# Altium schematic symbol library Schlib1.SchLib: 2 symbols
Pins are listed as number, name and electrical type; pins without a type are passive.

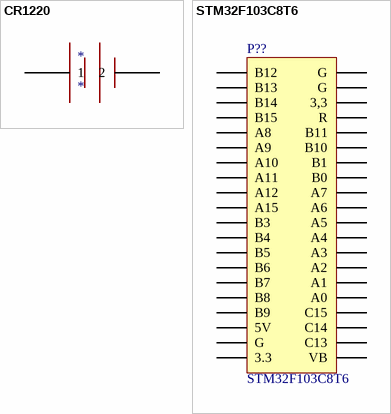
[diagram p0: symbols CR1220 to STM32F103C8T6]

## CR1220
designator *
纽扣电池
footprint CR1220 (纽扣电池)
pins: 1, 2

## STM32F103C8T6
designator P??
最小系统板
footprint HDR2X20 (Connector; Header; 20x2 Position)
signal-integrity model Connector
pins: 1 B12, 2 B13, 3 B14, 4 B15, 5 A8, 6 A9, 7 A10, 8 A11, 9 A12, 10 A15, 11 B3, 12 B4, 13 B5, 14 B6, 15 B7, 16 B8, 17 B9, 18 5V, 19 G, 20 3.3, 21 VB, 22 C13, 23 C14, 24 C15, 25 A0, 26 A1, 27 A2, 28 A3, 29 A4, 30 A5, 31 A6, 32 A7, 33 B0, 34 B1, 35 B10, 36 B11, 37 R, 38 3,3, 39 G, 40 G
